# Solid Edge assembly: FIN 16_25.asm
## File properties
Title: Zylinder
Author: bmolnar
Template: iso assembly.asm
Last saved by: bmolnar
Revision: 10
Application: Solid Edge
Username: bmolnar
Dokumentum tartalom típus: 1
Document Number: FIN 16/25
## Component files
Kolbenstange.par
Profilrohr.par
Kit_1.par
Kit_2.par
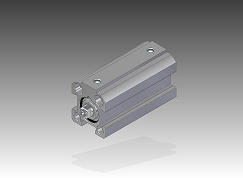
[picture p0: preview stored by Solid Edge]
